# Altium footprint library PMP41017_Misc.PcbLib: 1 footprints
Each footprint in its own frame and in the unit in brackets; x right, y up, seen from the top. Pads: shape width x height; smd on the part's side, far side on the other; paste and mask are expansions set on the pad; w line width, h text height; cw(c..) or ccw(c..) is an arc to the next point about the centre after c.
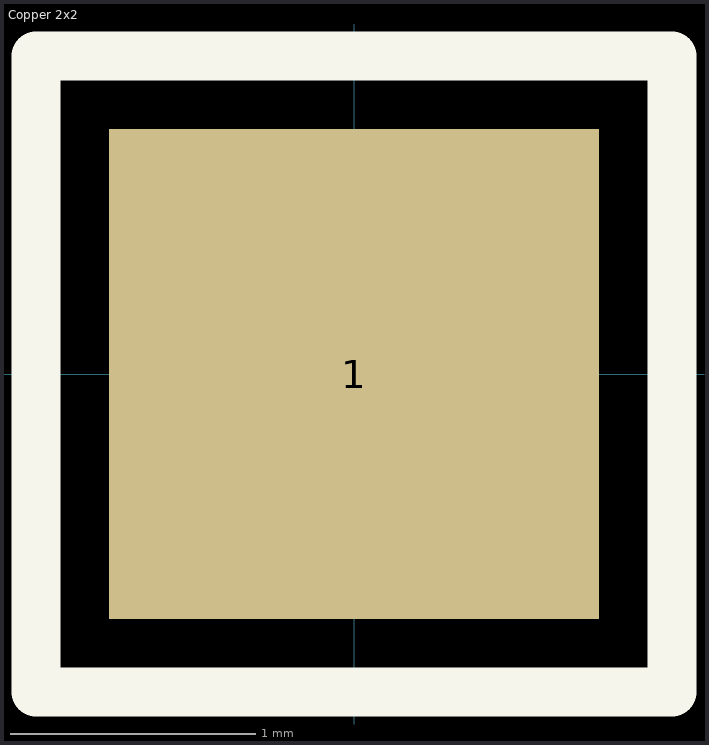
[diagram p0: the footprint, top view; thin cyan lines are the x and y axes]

## Copper 2x2 [mm] "copper 2mmx2mmx2mm"
pads (1):
  rect 2x2 smd: 1(0,0)
Top Overlay:
  lines w0.2: -1.3,-1.3 1.3,-1.3 1.3,1.3 -1.3,1.3 -1.3,-1.3
M5 Assembly Top:
  text ".Designator" at -1.8,-0.514 h1.02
